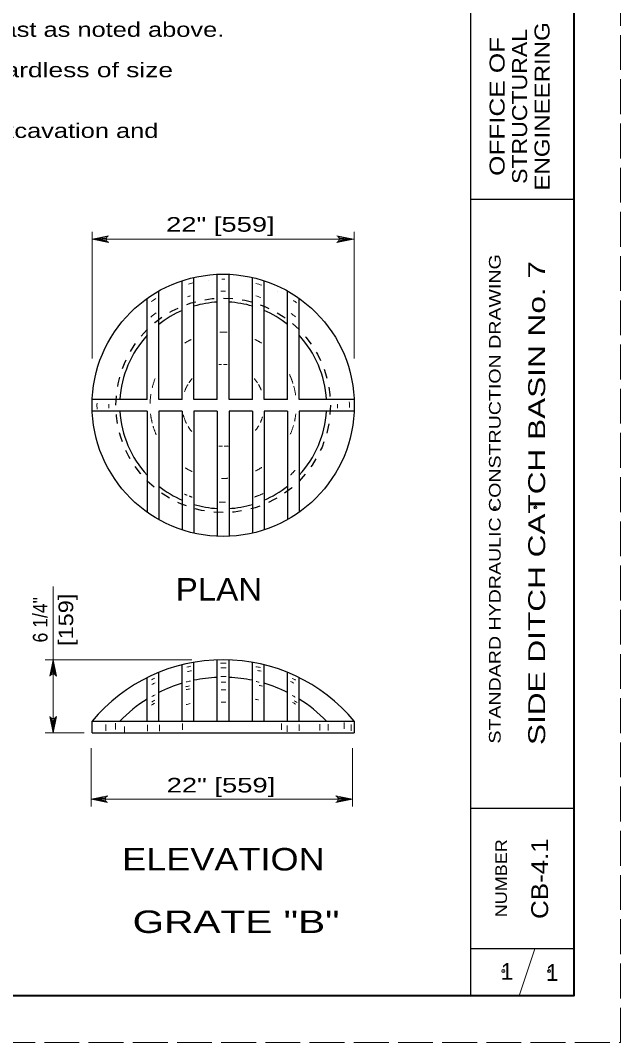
# Model space of a CAD drawing. Extents: x 1302.9 to 1336.9, y 688.5 to 710.5.
# Drawn here: x 1330.47 to 1336.88, y 688.5 to 699.41 of the extents above; entities that cross this region are included whole.
import ezdxf
from ezdxf.enums import TextEntityAlignment as Align

# ---------------------------------------------------------------- set-up
doc = ezdxf.new("R2010")
doc.units = 0
doc.header["$LTSCALE"] = 0.062
doc.header["$PDMODE"] = 32
doc.header["$PDSIZE"] = 0.031
doc.linetypes.add('LONG_DASHED', pattern=[7.5, 6, -1.5])
doc.linetypes.add('SHORT_DASHED', pattern=[2.7, 1.5, -1.2])
doc.layers.add('1', color=7, linetype='Continuous', lineweight=13)

msp = doc.modelspace()

# ---------------------------------------------------------------- linework, layer by layer
at = {"layer": '1', "lineweight": 25}
for p, q in [((1335.2765, 689.00158), (1335.2765, 710.00158)), ((1336.3765, 710.00158), (1336.3765, 689.00158)), ((1336.3765, 697.50158), (1335.2765, 697.50158)), ((1332.32083, 695.36733), (1332.32083, 696.66992)), ((1332.57067, 695.36733), (1332.57067, 696.70383)), ((1332.69567, 695.36733), (1332.69567, 696.70383)), ((1332.9455, 695.36733), (1332.9455, 696.66992)), ((1332.19583, 695.36733), (1332.19583, 696.63517)), ((1333.07042, 695.36733), (1333.07042, 696.63517)), ((1331.82108, 695.36733), (1331.82108, 696.44567)), ((1331.946, 695.36733), (1331.946, 696.525)), ((1333.32033, 695.36733), (1333.32033, 696.525)), ((1333.44525, 695.36733), (1333.44525, 696.44575)), ((1331.82108, 695.36733), (1331.23425, 695.36733)), ((1332.19583, 695.36733), (1331.946, 695.36733)), ((1332.57067, 695.36733), (1332.32083, 695.36733)), ((1332.9455, 695.36733), (1332.69567, 695.36733)), ((1333.32033, 695.36733), (1333.07042, 695.36733)), ((1334.03225, 695.36733), (1333.44525, 695.36733)), ((1331.82108, 695.24258), (1331.23425, 695.24258)), ((1331.82108, 695.24258), (1331.82108, 694.16425)), ((1331.946, 695.24258), (1331.946, 694.08492)), ((1332.19583, 695.24258), (1331.946, 695.24258)), ((1332.19583, 695.24258), (1332.19583, 693.97475)), ((1332.32083, 695.24258), (1332.32083, 693.94)), ((1332.57067, 695.24258), (1332.32083, 695.24258)), ((1332.57067, 695.24258), (1332.57067, 693.90608)), ((1332.69567, 695.24258), (1332.69567, 693.90608)), ((1332.9455, 695.24258), (1332.69567, 695.24258)), ((1332.9455, 695.24258), (1332.9455, 693.94)), ((1333.07042, 695.24258), (1333.07042, 693.97475)), ((1333.32033, 695.24258), (1333.07042, 695.24258)), ((1333.32033, 695.24258), (1333.32033, 694.08492)), ((1333.44525, 695.24258), (1333.44525, 694.16417)), ((1334.03225, 695.24258), (1333.44525, 695.24258)), ((1332.19592, 691.93217), (1332.19592, 692.53542)), ((1332.32092, 691.93217), (1332.32092, 692.56158)), ((1332.57075, 691.93217), (1332.57075, 692.5875)), ((1332.69575, 691.93217), (1332.69575, 692.5875)), ((1332.94558, 691.93217), (1332.94558, 692.56158)), ((1333.0705, 691.93217), (1333.0705, 692.53542)), ((1331.82117, 691.93217), (1331.82117, 692.39767)), ((1331.94608, 691.93217), (1331.94608, 692.45408)), ((1333.32042, 691.93217), (1333.32042, 692.45408)), ((1333.44533, 691.93217), (1333.44533, 692.39767)), ((1331.23292, 691.80725), (1334.03367, 691.80725)), ((1336.3765, 691.00158), (1335.2765, 691.00158)), ((1336.3765, 689.50158), (1335.2765, 689.50158))]:
    msp.add_line(p, q, dxfattribs=at)
at = {"layer": '1'}
for p, q in [((1331.23283, 695.80467), (1331.23283, 697.15808)), ((1331.39308, 697.10233), (1331.23283, 697.07992)), ((1331.38767, 697.09125), (1331.23283, 697.07992)), ((1333.86492, 697.10233), (1334.02517, 697.07992)), ((1333.87033, 697.09125), (1334.02517, 697.07992)), ((1334.03367, 695.80467), (1334.03367, 697.15808)), ((1332.88983, 697.07992), (1331.23283, 697.07992)), ((1331.386, 697.07992), (1331.23283, 697.07992)), ((1331.38883, 697.0655), (1331.23283, 697.07992)), ((1331.39492, 697.05517), (1331.23283, 697.07992)), ((1332.88983, 697.07992), (1334.02517, 697.07992)), ((1333.86308, 697.05517), (1334.02517, 697.07992)), ((1333.86917, 697.0655), (1334.02517, 697.07992)), ((1333.872, 697.07992), (1334.02517, 697.07992)), ((1332.30008, 692.58858), (1330.73317, 692.58858)), ((1330.79167, 692.4265), (1330.81642, 692.58858)), ((1330.802, 692.43258), (1330.81642, 692.58858)), ((1330.81642, 692.43542), (1330.81642, 692.58858)), ((1330.82775, 692.43375), (1330.81642, 692.58858)), ((1330.83883, 692.42833), (1330.81642, 692.58858)), ((1330.794, 691.9675), (1330.81642, 691.80725)), ((1330.80508, 691.962), (1330.81642, 691.80725)), ((1330.84125, 691.96933), (1330.81642, 691.80725)), ((1330.83083, 691.96325), (1330.81642, 691.80725)), ((1330.81642, 691.96042), (1330.81642, 691.80725)), ((1331.379, 691.83025), (1331.379, 691.89767)), ((1331.4825, 691.8445), (1331.4825, 691.912)), ((1331.57958, 691.80758), (1331.57958, 691.875)), ((1331.82542, 691.827), (1331.82542, 691.89442)), ((1331.95158, 691.827), (1331.95158, 691.89442)), ((1332.20058, 691.83992), (1332.20058, 691.90742)), ((1333.25492, 691.83992), (1333.25492, 691.90742)), ((1333.31633, 691.82058), (1333.31633, 691.888)), ((1333.44575, 691.83025), (1333.44575, 691.89767)), ((1333.66567, 691.83342), (1333.66567, 691.90092)), ((1333.753, 691.83342), (1333.753, 691.90092)), ((1333.92442, 691.84967), (1333.92442, 691.91717)), ((1333.99875, 691.83025), (1333.99875, 691.89767)), ((1331.14958, 691.80725), (1330.73317, 691.80725)), ((1331.22233, 691.64583), (1331.22233, 691.02117)), ((1334.01467, 691.64583), (1334.01467, 691.02117)), ((1331.38258, 691.12175), (1331.22233, 691.09933)), ((1331.37717, 691.11058), (1331.22233, 691.09933)), ((1332.87942, 691.09933), (1331.22233, 691.09933)), ((1331.3755, 691.09933), (1331.22233, 691.09933)), ((1331.37833, 691.08492), (1331.22233, 691.09933)), ((1331.3845, 691.0745), (1331.22233, 691.09933)), ((1332.87942, 691.09933), (1334.01467, 691.09933)), ((1333.85258, 691.0745), (1334.01467, 691.09933)), ((1333.85442, 691.12175), (1334.01467, 691.09933)), ((1333.85867, 691.08492), (1334.01467, 691.09933)), ((1333.85983, 691.11058), (1334.01467, 691.09933)), ((1333.8615, 691.09933), (1334.01467, 691.09933)), ((1335.79317, 689.00158), (1335.95983, 689.50158))]:
    msp.add_line(p, q, dxfattribs=at)
at = {"layer": '1', "linetype": 'LONG_DASHED'}
msp.add_lwpolyline([(1302.8765, 688.50158), (1336.8765, 688.50158), (1336.8765, 710.50158), (1302.8765, 710.50158)], close=True, dxfattribs=at)
at = {"layer": '1', "lineweight": 25}
for points in [[(1336.3765, 689.00158), (1304.8765, 689.00158), (1304.8765, 710.00158)], [(1331.23292, 691.80725), (1331.23292, 691.93217), (1334.03367, 691.93217), (1334.03367, 691.80725)]]:
    msp.add_lwpolyline(points, dxfattribs=at)
at = {"layer": '1', "lineweight": 40}
msp.add_lwpolyline([(1304.8765, 710.00158), (1336.3765, 710.00158), (1336.3765, 689.00158), (1304.8765, 689.00158)], close=True, dxfattribs=at)
msp.add_lwpolyline([(1304.8765, 710.00158), (1336.3765, 710.00158), (1336.3765, 689.00158), (1304.8765, 689.00158)], close=True, dxfattribs=at)
at = {"layer": '1'}
for points in [[(1331.40983, 697.0445), (1331.23283, 697.07992), (1331.40983, 697.11533)], [(1333.84817, 697.0445), (1334.02517, 697.07992), (1333.84817, 697.11533)], [(1330.81642, 691.80725), (1330.81642, 692.01808), (1330.81642, 693.3695)], [(1330.781, 692.41158), (1330.81642, 692.58858), (1330.85183, 692.41158)], [(1330.85183, 691.98425), (1330.81642, 691.80725), (1330.781, 691.98425)], [(1331.39933, 691.06392), (1331.22233, 691.09933), (1331.39933, 691.13467)], [(1333.83767, 691.06392), (1334.01467, 691.09933), (1333.83767, 691.13467)]]:
    msp.add_lwpolyline(points, dxfattribs=at)
for centre, start, end in [((1331.42412, 697.08001), 112.08782, 247.91395), ((1333.83388, 697.08001), 292.08605, 67.91218), ((1330.81648, 692.39735), 22.08782, 157.91395), ((1330.8164, 691.99855), 202.08782, 337.91395), ((1331.41362, 691.09937), 112.08782, 247.91395), ((1333.82339, 691.09937), 292.08605, 67.91218)]:
    msp.add_arc(centre, 0.0382, start, end, dxfattribs=at)
at = {"layer": '1', "lineweight": 25}
msp.add_ellipse((1332.6332, 695.30499), major_axis=(1.40038, 0), ratio=0.999895, dxfattribs=at)
at = {"layer": '1'}
for centre, major_axis, start_param, end_param in [((1332.63316, 695.30499), (1.34742, 0), 1.55722979, 1.58155667), ((1332.63316, 695.30499), (1.34742, 0), 1.81351364, 1.85041145), ((1332.63316, 695.30499), (1.34742, 0), 1.69032835, 1.6903476), ((1332.63316, 695.30499), (1.34742, 0), 1.25953756, 1.30916803), ((1332.63316, 695.30499), (1.34742, 0), 2.13375548, 2.1771144), ((1332.63316, 695.30499), (1.21982, 0), 1.86179216, 1.88772145), ((1332.63316, 695.30499), (1.21982, 0), 1.54940882, 1.59216754), ((1332.63316, 695.30499), (1.21982, 0), 1.23497054, 1.2809158), ((1332.63316, 695.30499), (1.34742, 0), 1.12279707, 1.12281733), ((1332.63316, 695.30499), (1.34742, 0), 0.94919557, 0.98075107), ((1332.63316, 695.30499), (1.21982, 0), 2.19826449, 2.25826164), ((1332.63316, 695.30499), (1.21982, 0), 0.8861215, 0.93470158), ((1332.63316, 695.30499), (1.34742, 0), 6.26536966, 6.31030515), ((1332.63316, 695.30499), (1.34742, 0), 3.12559026, 3.17214711), ((1332.63316, 695.30499), (1.21982, 0), 3.13099734, 3.16655784), ((1332.63316, 695.30499), (1.21982, 0), 6.25740956, 6.29321654), ((1332.61821, 690.7882), (-1.76165, 0), 4.90127346, 4.92604298), ((1332.63629, 690.78978), (-1.76165, 0), 4.69656854, 4.7295542), ((1332.63787, 690.74206), (-1.76165, 0), 4.69656854, 4.7295542), ((1332.75731, 690.76705), (-1.76165, 0), 4.55518863, 4.58473448), ((1332.64387, 690.79428), (-1.76165, 0), 5.14681345, 5.16956557), ((1332.62571, 690.74056), (-1.76165, 0), 4.90127346, 4.92604298), ((1332.63787, 690.74206), (-1.66665, 0), 4.69656854, 4.7295542), ((1332.76189, 690.72765), (-1.76165, 0), 4.55518863, 4.57710439), ((1332.64995, 690.74431), (-1.76165, 0), 5.14681345, 5.16956557), ((1332.60364, 690.57857), (-1.76165, 0), 4.90127346, 4.92604298), ((1332.6133, 690.63037), (-1.76165, 0), 4.90127346, 4.92604298), ((1332.63787, 690.74206), (-1.60906, 0), 4.69656854, 4.7295542), ((1332.61097, 690.75716), (-1.6428, 0), 4.46154793, 4.48346369), ((1332.64496, 690.71501), (-1.6428, 0), 4.46154793, 4.48346369), ((1332.63787, 690.74581), (-1.76165, 0), 4.27260024, 4.29389194), ((1332.63779, 690.78678), (-1.76165, 0), 4.26138965, 4.28352076), ((1332.75031, 690.66828), (-1.76165, 0), 5.21098412, 5.23373623), ((1332.61013, 690.54776), (-1.76165, 0), 4.90127346, 4.92604298), ((1332.63787, 690.74206), (-1.5242, 0), 4.69656854, 4.7295542), ((1334.19185, 693.76501), (1.76165, 0), 4.22721062, 4.24850233), ((1332.74548, 690.57758), (-1.76165, 0), 5.21098412, 5.23373623), ((1332.74706, 690.60998), (-1.76165, 0), 5.21098412, 5.23373623), ((1332.65448, 690.39838), (-1.76165, 0), 4.92611652, 4.95088604), ((1332.6362, 690.61089), (-1.5242, 0), 4.69656854, 4.7295542), ((1332.60289, 690.56768), (-1.6428, 0), 4.46154793, 4.48346369), ((1334.19668, 693.69047), (1.76165, 0), 4.22721062, 4.24850233), ((1334.21126, 693.7083), (1.76165, 0), 4.22721062, 4.24850233)]:
    msp.add_ellipse(centre, major_axis=major_axis, ratio=0.999895, start_param=start_param, end_param=end_param, dxfattribs=at)
at = {"layer": '1', "linetype": 'SHORT_DASHED', "lineweight": 25}
msp.add_ellipse((1332.63316, 695.30499), major_axis=(1.14529, 0), ratio=0.999895, dxfattribs=at)
at = {"layer": '1', "lineweight": 25}
for centre, major_axis, start_param, end_param in [((1332.63316, 695.30499), (1.10365, 0), 1.62742935, 1.85774218), ((1332.63316, 695.30499), (1.10365, 0), 1.28385048, 1.5141633), ((1332.63316, 695.30499), (1.10365, 0), 1.97818531, 2.24292059), ((1332.63316, 695.30499), (1.10365, 0), 0.89867207, 1.16340734), ((1332.63316, 695.30499), (1.10365, 0), 2.39771602, 3.08503502), ((1332.63316, 695.30499), (1.10365, 0), 0.05655764, 0.74386665), ((1332.63316, 695.30499), (1.10365, 0), 3.19830102, 3.88546929), ((1332.63316, 695.30499), (1.10365, 0), 5.53931866, 6.22647694), ((1332.63316, 695.30499), (1.10365, 0), 4.04026472, 4.305), ((1332.63316, 695.30499), (1.10365, 0), 5.11977797, 5.38451324), ((1332.63316, 695.30499), (1.10365, 0), 4.42544313, 4.65575596), ((1332.63316, 695.30499), (1.10365, 0), 4.76902201, 4.99933483), ((1332.63329, 690.76705), (-1.82179, 0), 3.83560465, 5.58917336), ((1332.63325, 690.86862), (1.53279, 0), 1.61156373, 1.77601418), ((1332.63325, 690.86862), (-1.53279, 0), 4.50717113, 4.67162158), ((1332.63325, 690.86862), (1.53279, 0), 1.86010802, 2.03567791), ((1332.63325, 690.86862), (-1.53279, 0), 4.2475074, 4.42307729), ((1332.63325, 690.86862), (1.53279, 0), 2.12919542, 2.37463351), ((1332.63325, 690.86862), (-1.53279, 0), 3.9085518, 4.15398989)]:
    msp.add_ellipse(centre, major_axis=major_axis, ratio=0.999895, start_param=start_param, end_param=end_param, dxfattribs=at)
at = {"layer": '1', "linetype": 'SHORT_DASHED'}
for centre, major_axis, start_param, end_param in [((1332.63325, 695.30499), (0.78088, 0), 2.02185815, 2.12318591), ((1332.63325, 695.30499), (0.78088, 0), 1.51828461, 1.61749033), ((1332.63325, 695.30499), (0.78088, 0), 1.01906236, 1.12233756), ((1332.63325, 695.30499), (0.43729, 0), 1.61150041, 1.6784096), ((1332.63325, 695.30499), (0.43729, 0), 1.47112765, 1.56564959), ((1332.63325, 695.30499), (0.78088, 0), 2.76526612, 2.94462119), ((1332.63325, 695.30499), (0.43729, 0), 2.42905006, 2.55652023), ((1332.63325, 695.30499), (0.43729, 0), 0.58018526, 0.70777358), ((1332.63325, 695.30499), (0.78088, 0), 0.3050709, 0.43617291), ((1332.63325, 695.30499), (0.43729, 0), 2.60445696, 2.8038857), ((1332.63325, 695.30499), (0.43729, 0), 0.38214328, 0.53070149), ((1332.63325, 695.30499), (0.78088, 0), 0.13923573, 0.26304201), ((1332.63325, 695.30499), (0.78088, 0), 2.98934763, 3.12316542), ((1332.63325, 695.30499), (0.78088, 0), 3.26044255, 3.39392508), ((1332.63325, 695.30499), (0.43729, 0), 3.37669253, 3.61578678), ((1332.63325, 695.30499), (0.43729, 0), 5.85077751, 5.99650703), ((1332.63325, 695.30499), (0.78088, 0), 6.06471275, 6.16784973), ((1332.63325, 695.30499), (0.78088, 0), 3.42945218, 3.57045535), ((1332.63325, 695.30499), (0.43729, 0), 3.68624185, 3.83825013), ((1332.63325, 695.30499), (0.43729, 0), 5.61950781, 5.76134282), ((1332.63325, 695.30499), (0.78088, 0), 5.875939, 6.02671082), ((1332.63325, 695.30499), (0.43729, 0), 4.60687946, 4.69629191), ((1332.63325, 695.30499), (0.43729, 0), 4.73271295, 4.83080172), ((1332.63325, 695.30499), (0.78088, 0), 4.16755973, 4.2763811), ((1332.63325, 695.30499), (0.78088, 0), 5.16869164, 5.27010317), ((1332.63316, 695.30499), (1.0348, 0), 5.48120409, 5.54754764), ((1332.63325, 695.30499), (0.78088, 0), 4.68713387, 4.7744094), ((1332.63316, 695.30499), (1.0348, 0), 4.3006054, 4.3308667), ((1332.63316, 695.30499), (1.0348, 0), 5.041203, 5.13672792), ((1332.63316, 695.30499), (1.0348, 0), 4.35276059, 4.38699042), ((1332.63316, 695.30499), (1.0348, 0), 4.67059125, 4.73581377)]:
    msp.add_ellipse(centre, major_axis=major_axis, ratio=0.999895, start_param=start_param, end_param=end_param, dxfattribs=at)
at = {"layer": '1'}
for p in [(1335.53392, 694.20758), (1335.96675, 694.21492), (1335.62458, 689.26533), (1336.113, 689.26433)]:
    msp.add_point(p, dxfattribs=at)

# ---------------------------------------------------------------- texts
for s, height, width, p in [('pipe having bell and spigot ends, or precast as noted above.', 0.156, 1.3, (1325.40817, 699.239)), ('             Diameter shall be 18" [450] regardless of size ', 0.156, 1.35, (1325.40817, 698.8075)), ('          All materials and labor, including excavation and', 0.156, 1.3, (1325.38417, 698.15942)), ('PLAN', 0.24, 1.1, (1332.12717, 693.22058)), ('ELEVATION', 0.24, 1.2, (1331.55475, 690.33883)), ('GRATE "B"', 0.24, 1.35, (1331.66608, 689.67133))]:
    msp.add_text(s, height=height, dxfattribs=dict(at, width=width)).set_placement(p)
for s, height, width, p in [('ENGINEERING', 0.16, 1.2, (1336.11825, 698.49613)), ('STRUCTURAL', 0.16, 1.15, (1335.87825, 698.49604)), ('OFFICE OF', 0.16, 1.3, (1335.63825, 698.49604)), ('STANDARD HYDRAULIC CONSTRUCTION DRAWING', 0.125, 1.25, (1335.59642, 694.30562)), ('SIDE DITCH CATCH BASIN No. 7', 0.18, 1.4, (1336.07108, 694.26175)), ('[159]', 0.156, 1.2, (1331.03125, 693.01521)), ('6 1/4"', 0.156, 0.9, (1330.75725, 693.01513)), ('NUMBER', 0.125, 1.15, (1335.6635, 690.25567)), ('CB-4.1', 0.18, 1.15, (1336.10308, 690.25192))]:
    msp.add_text(s, height=height, rotation=90, dxfattribs=dict(at, width=width)).set_placement(p, align=Align.CENTER)
at = {"layer": '1', "width": 1.4}
for p in [(1332.60337, 697.15842), (1332.60946, 691.1715)]:
    msp.add_text('22" [559]', height=0.156, dxfattribs=at).set_placement(p, align=Align.CENTER)
at = {"layer": '1'}
for p in [(1335.66435, 689.17167), (1336.14718, 689.15908)]:
    msp.add_text('1', height=0.18, dxfattribs=at).set_placement(p, align=Align.CENTER)

doc.saveas('drawing.dxf')
